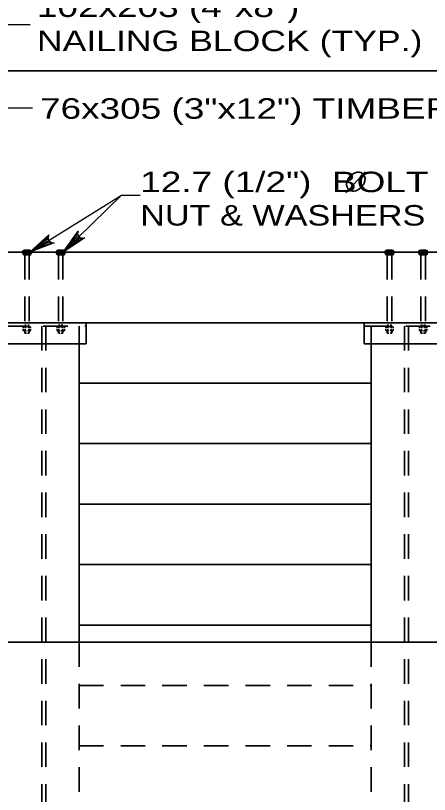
# Model space of a CAD drawing. Extents: x -6.4 to 73.1, y -66 to 0.
# Drawn here: x 44.097 to 46.524, y -63.125 to -58.56 of the extents above; entities that cross this region are included whole.
import ezdxf

# ---------------------------------------------------------------- set-up
doc = ezdxf.new("R2010")
doc.units = 0
doc.header["$LTSCALE"] = 0.048
doc.header["$PDMODE"] = 32
doc.header["$PDSIZE"] = 0.024
doc.linetypes.add('MEDIUM_DASHED', pattern=[4.5, 3, -1.5])
for name, color, linetype, lineweight in [('3', 7, 'Continuous', 35), ('4', 7, 'Continuous', 25), ('5', 7, 'Continuous', 25), ('52', 7, 'Continuous', 25), ('8', 7, 'Continuous', 25)]:
    doc.layers.add(name, color=color, linetype=linetype, lineweight=lineweight)

msp = doc.modelspace()

# ---------------------------------------------------------------- linework, layer by layer
at = {"layer": '3'}
for p, q in [((42.61283, -58.88358), (48.03658, -58.88358)), ((41.76775, -59.9465), (48.03658, -59.9465)), ((44.1425, -59.96242), (44.1425, -59.95025)), ((44.18017, -59.9465), (44.14783, -59.9465)), ((44.1535, -59.95025), (44.1535, -59.96242)), ((44.17483, -59.95025), (44.17483, -59.96242)), ((44.34033, -59.96242), (44.34033, -59.95025)), ((44.383, -59.96242), (44.34033, -59.96242)), ((44.34525, -59.9465), (44.37767, -59.9465)), ((44.35058, -59.95025), (44.35058, -59.96242)), ((44.37192, -59.95025), (44.37192, -59.96242)), ((44.383, -59.96242), (44.383, -59.95025)), ((46.2685, -59.96242), (46.2685, -59.95025)), ((46.30617, -59.9465), (46.27383, -59.9465)), ((46.2795, -59.95025), (46.2795, -59.96242)), ((46.30083, -59.95025), (46.30083, -59.96242)), ((46.46633, -59.96242), (46.46633, -59.95025)), ((46.50892, -59.96242), (46.46633, -59.96242)), ((46.47125, -59.9465), (46.50358, -59.9465)), ((46.47658, -59.95025), (46.47658, -59.96242)), ((46.49792, -59.95025), (46.49792, -59.96242)), ((46.50892, -59.96242), (46.50892, -59.95025)), ((41.76775, -60.35992), (48.03658, -60.35992)), ((44.14208, -60.39133), (44.14208, -60.386)), ((44.17983, -60.38225), (44.14742, -60.38225)), ((44.15958, -60.375), (44.15067, -60.375)), ((44.15317, -60.386), (44.15317, -60.39133)), ((44.17692, -60.375), (44.16858, -60.375)), ((44.1745, -60.386), (44.1745, -60.39133)), ((44.18475, -60.39133), (44.18475, -60.386)), ((44.34067, -60.39192), (44.34067, -60.386)), ((44.34567, -60.38225), (44.378, -60.38225)), ((44.3485, -60.375), (44.358, -60.375)), ((44.351, -60.386), (44.351, -60.39192)), ((44.36517, -60.375), (44.37475, -60.375)), ((44.37233, -60.386), (44.37233, -60.39192)), ((44.38333, -60.39192), (44.38333, -60.386)), ((44.51033, -60.35992), (44.51033, -60.48292)), ((46.14117, -60.35992), (46.14117, -60.48292)), ((46.26808, -60.39133), (46.26808, -60.386)), ((46.30583, -60.38225), (46.27342, -60.38225)), ((46.28558, -60.375), (46.27667, -60.375)), ((46.27917, -60.386), (46.27917, -60.39133)), ((46.30292, -60.375), (46.29458, -60.375)), ((46.3005, -60.386), (46.3005, -60.39133)), ((46.31075, -60.39133), (46.31075, -60.386)), ((46.46667, -60.39192), (46.46667, -60.386)), ((46.47167, -60.38225), (46.504, -60.38225)), ((46.4745, -60.375), (46.484, -60.375)), ((46.477, -60.386), (46.477, -60.39192)), ((46.49117, -60.375), (46.50075, -60.375)), ((46.49833, -60.386), (46.49833, -60.39192)), ((46.50933, -60.39192), (46.50933, -60.386)), ((44.14208, -60.40433), (44.14208, -60.39808)), ((44.1585, -60.40808), (44.14742, -60.40808)), ((44.15067, -60.40808), (44.15067, -60.42092)), ((44.16017, -60.42092), (44.15067, -60.42092)), ((44.15317, -60.39808), (44.15317, -60.40433)), ((44.17692, -60.42092), (44.16742, -60.42092)), ((44.17983, -60.40808), (44.169, -60.40808)), ((44.1745, -60.39808), (44.1745, -60.40433)), ((44.17692, -60.40808), (44.17692, -60.42092)), ((44.18475, -60.40433), (44.18475, -60.39808)), ((44.34067, -60.40433), (44.34067, -60.398)), ((44.34567, -60.40808), (44.358, -60.40808)), ((44.3485, -60.40808), (44.3485, -60.42092)), ((44.3485, -60.42092), (44.358, -60.42092)), ((44.351, -60.398), (44.351, -60.40433)), ((44.364, -60.40808), (44.378, -60.40808)), ((44.364, -60.42092), (44.37475, -60.42092)), ((44.37233, -60.398), (44.37233, -60.40433)), ((44.37475, -60.40808), (44.37475, -60.42092)), ((44.38333, -60.40433), (44.38333, -60.398)), ((46.26808, -60.40433), (46.26808, -60.39808)), ((46.2845, -60.40808), (46.27342, -60.40808)), ((46.27667, -60.40808), (46.27667, -60.42092)), ((46.28617, -60.42092), (46.27667, -60.42092)), ((46.27917, -60.39808), (46.27917, -60.40433)), ((46.30292, -60.42092), (46.29342, -60.42092)), ((46.30583, -60.40808), (46.295, -60.40808)), ((46.3005, -60.39808), (46.3005, -60.40433)), ((46.30292, -60.40808), (46.30292, -60.42092)), ((46.31075, -60.40433), (46.31075, -60.39808)), ((46.46667, -60.40433), (46.46667, -60.398)), ((46.47167, -60.40808), (46.484, -60.40808)), ((46.4745, -60.40808), (46.4745, -60.42092)), ((46.4745, -60.42092), (46.484, -60.42092)), ((46.477, -60.398), (46.477, -60.40433)), ((46.49, -60.40808), (46.504, -60.40808)), ((46.49, -60.42092), (46.50075, -60.42092)), ((46.49833, -60.398), (46.49833, -60.40433)), ((46.50075, -60.40808), (46.50075, -60.42092)), ((46.50933, -60.40433), (46.50933, -60.398)), ((44.01517, -60.48292), (44.51033, -60.48292)), ((44.46933, -60.48292), (44.46933, -62.23267)), ((46.14117, -60.48292), (46.63633, -60.48292)), ((46.18208, -60.48292), (46.18208, -62.23267)), ((44.46933, -60.71425), (46.18208, -60.71425)), ((44.46933, -61.06858), (46.18208, -61.06858)), ((44.46933, -61.42292), (46.18208, -61.42292)), ((44.46933, -61.77725), (46.18208, -61.77725)), ((44.46933, -62.13158), (46.18208, -62.13158)), ((42.0525, -62.23267), (48.03658, -62.23267))]:
    msp.add_line(p, q, dxfattribs=at)
at = {"layer": '3', "linetype": 'MEDIUM_DASHED'}
for p, q in [((44.15067, -59.96242), (44.15067, -60.38225)), ((44.17692, -59.96242), (44.17692, -60.38225)), ((44.3485, -59.96242), (44.3485, -60.38225)), ((44.37475, -59.96242), (44.37475, -60.38225)), ((46.27667, -59.96242), (46.27667, -60.38225)), ((46.30292, -59.96242), (46.30292, -60.38225)), ((46.4745, -59.96242), (46.4745, -60.38225)), ((46.50075, -59.96242), (46.50075, -60.38225)), ((44.46933, -62.23267), (44.46933, -64.0185)), ((46.18208, -62.23267), (46.18208, -64.00542)), ((44.46933, -62.48592), (46.18208, -62.48592)), ((44.46933, -62.84025), (46.18208, -62.84025))]:
    msp.add_line(p, q, dxfattribs=at)
at = {"layer": '3'}
for points in [[(44.1425, -59.96242), (44.18517, -59.96242), (44.18517, -59.95025)], [(46.2685, -59.96242), (46.31108, -59.96242), (46.31108, -59.95025)]]:
    msp.add_lwpolyline(points, dxfattribs=at)
for centre, radius, start, end in [((44.14806, -59.95239), 0.00592, 88.17294, 158.71305), ((44.14806, -59.95239), 0.00592, 21.28694, 88.17294), ((44.16424, -59.96343), 0.01696, 51.05, 128.95), ((44.18005, -59.95186), 0.00539, 17.45181, 162.54819), ((44.34552, -59.95186), 0.00539, 17.45181, 162.54819), ((44.36132, -59.96343), 0.01696, 51.05, 128.95), ((44.37751, -59.95239), 0.00592, 91.82706, 158.71306), ((44.37751, -59.95239), 0.00592, 21.28694, 91.82706), ((46.27403, -59.95242), 0.00592, 88.17294, 158.71305), ((46.27403, -59.95242), 0.00592, 21.28694, 88.17294), ((46.29021, -59.96346), 0.01696, 51.05, 128.95), ((46.30601, -59.95188), 0.00539, 17.45181, 162.54819), ((46.47149, -59.95188), 0.00539, 17.45181, 162.54819), ((46.48729, -59.96346), 0.01696, 51.05, 128.95), ((46.50347, -59.95242), 0.00592, 91.82706, 158.71306), ((46.50347, -59.95242), 0.00592, 21.28694, 91.82706), ((44.14765, -60.38818), 0.00592, 88.17294, 158.71305), ((44.14765, -60.38818), 0.00592, 21.28694, 88.17294), ((44.16383, -60.39922), 0.01696, 51.05, 128.95), ((44.17964, -60.38764), 0.00539, 17.45181, 162.54819), ((44.34587, -60.38764), 0.00539, 17.45181, 162.54819), ((44.36167, -60.39922), 0.01696, 51.05, 128.95), ((44.37785, -60.38818), 0.00592, 91.82706, 158.71306), ((44.37785, -60.38818), 0.00592, 21.28694, 91.82706), ((46.27365, -60.38818), 0.00592, 88.17294, 158.71305), ((46.27365, -60.38818), 0.00592, 21.28694, 88.17294), ((46.28983, -60.39922), 0.01696, 51.05, 128.95), ((46.30564, -60.38764), 0.00539, 17.45181, 162.54819), ((46.47187, -60.38764), 0.00539, 17.45181, 162.54819), ((46.48767, -60.39922), 0.01696, 51.05, 128.95), ((46.50385, -60.38818), 0.00592, 91.82706, 158.71306), ((46.50385, -60.38818), 0.00592, 21.28694, 91.82706), ((44.14765, -60.40216), 0.00592, 201.28694, 271.82706), ((44.14765, -60.40216), 0.00592, 271.82706, 338.71306), ((44.16383, -60.39113), 0.01696, 231.05, 256.0077), ((44.16383, -60.39113), 0.01696, 284.34274, 308.95), ((44.17964, -60.4027), 0.00539, 197.45181, 342.54819), ((44.34587, -60.4027), 0.00539, 197.45181, 342.54819), ((44.36167, -60.39113), 0.01696, 231.05, 257.49177), ((44.36167, -60.39113), 0.01696, 277.88621, 308.95), ((44.37785, -60.40216), 0.00592, 201.28694, 268.17294), ((44.37785, -60.40216), 0.00592, 268.17294, 338.71305), ((46.27365, -60.40216), 0.00592, 201.28694, 271.82706), ((46.27365, -60.40216), 0.00592, 271.82706, 338.71306), ((46.28983, -60.39113), 0.01696, 231.05, 256.0077), ((46.28983, -60.39113), 0.01696, 284.34274, 308.95), ((46.30564, -60.4027), 0.00539, 197.45181, 342.54819), ((46.47187, -60.4027), 0.00539, 197.45181, 342.54819), ((46.48767, -60.39113), 0.01696, 231.05, 257.49177), ((46.48767, -60.39113), 0.01696, 277.88621, 308.95), ((46.50385, -60.40216), 0.00592, 201.28694, 268.17294), ((46.50385, -60.40216), 0.00592, 268.17294, 338.71305)]:
    msp.add_arc(centre, radius, start, end, dxfattribs=at)
for p in [(44.14967, -59.94667), (44.15025, -59.94667), (44.15083, -59.94667), (44.15117, -59.94725), (44.15142, -59.94667), (44.15175, -59.94725), (44.152, -59.94667), (44.152, -59.94783), (44.15233, -59.94725), (44.15258, -59.94667), (44.15258, -59.94783), (44.15292, -59.94725), (44.15292, -59.94842), (44.15325, -59.94667), (44.15325, -59.94783), (44.15325, -59.949), (44.1535, -59.94725), (44.1535, -59.94842), (44.1535, -59.94958), (44.15383, -59.94667), (44.15383, -59.94783), (44.15383, -59.949), (44.15408, -59.94725), (44.15408, -59.94842), (44.15408, -59.94958), (44.15442, -59.94667), (44.15442, -59.94783), (44.15442, -59.949), (44.15467, -59.94725), (44.15467, -59.94842), (44.155, -59.94667), (44.155, -59.94783), (44.155, -59.949), (44.15525, -59.94725), (44.15525, -59.94842), (44.15558, -59.94667), (44.15558, -59.94783), (44.15583, -59.94725), (44.15583, -59.94842), (44.15617, -59.94667), (44.15617, -59.94783), (44.15642, -59.94725), (44.15675, -59.94667), (44.15675, -59.94783), (44.15708, -59.94725), (44.15733, -59.94667), (44.15733, -59.94783), (44.15758, -59.94725), (44.15792, -59.94667), (44.15825, -59.94725), (44.1585, -59.94667), (44.15883, -59.94725), (44.15908, -59.94667), (44.15967, -59.94667), (44.16033, -59.94667), (44.16092, -59.94667), (44.1615, -59.94667), (44.16675, -59.94667), (44.16742, -59.94667), (44.168, -59.94667), (44.16858, -59.94667), (44.16917, -59.94667), (44.16942, -59.94725), (44.16975, -59.94667), (44.17, -59.94725), (44.17033, -59.94667), (44.17067, -59.94725), (44.17092, -59.94667), (44.17092, -59.94783), (44.17125, -59.94725), (44.1715, -59.94667), (44.1715, -59.94783), (44.17183, -59.94725), (44.17208, -59.94667), (44.17208, -59.94783), (44.17242, -59.94725), (44.17242, -59.94842), (44.17275, -59.94667), (44.17275, -59.94783), (44.173, -59.94725), (44.173, -59.94842), (44.17325, -59.94667), (44.17325, -59.94783), (44.17325, -59.949), (44.17358, -59.94725), (44.17358, -59.94842), (44.17392, -59.94667), (44.17392, -59.94783), (44.17392, -59.949), (44.17417, -59.94725), (44.17417, -59.94842), (44.17417, -59.94958), (44.1745, -59.94667), (44.1745, -59.94783), (44.1745, -59.949), (44.17475, -59.94725), (44.17475, -59.94842), (44.17475, -59.94958), (44.17483, -59.94725), (44.17483, -59.94842), (44.17483, -59.94958), (44.17517, -59.94667), (44.17517, -59.94783), (44.17517, -59.949), (44.17542, -59.94842), (44.1755, -59.94725), (44.17575, -59.94667), (44.17575, -59.94783), (44.176, -59.94725), (44.17633, -59.94667), (44.17633, -59.94783), (44.17667, -59.94725), (44.17692, -59.94667), (44.17725, -59.94725), (44.1775, -59.94667), (44.17808, -59.94667), (44.17875, -59.94667), (44.34675, -59.94667), (44.34733, -59.94667), (44.34792, -59.94667), (44.34825, -59.94725), (44.3485, -59.94667), (44.34883, -59.94725), (44.34908, -59.94667), (44.34908, -59.94783), (44.34942, -59.94725), (44.34967, -59.94667), (44.34967, -59.94783), (44.35, -59.94725), (44.35, -59.94842), (44.35033, -59.94667), (44.35033, -59.94783), (44.35033, -59.949), (44.35058, -59.94725), (44.35058, -59.94842), (44.35058, -59.94958), (44.35067, -59.94725), (44.35067, -59.94842), (44.35067, -59.94958), (44.351, -59.94667), (44.351, -59.94783), (44.351, -59.949), (44.35133, -59.94725), (44.35133, -59.94842), (44.35133, -59.94958), (44.35158, -59.94667), (44.35158, -59.94783), (44.35158, -59.949), (44.35183, -59.94725), (44.35183, -59.94842), (44.35217, -59.94667), (44.35217, -59.94783), (44.35217, -59.949), (44.35242, -59.94725), (44.35242, -59.94842), (44.35275, -59.94667), (44.35275, -59.94783), (44.35308, -59.94725), (44.35308, -59.94842), (44.35333, -59.94667), (44.35333, -59.94783), (44.35367, -59.94725), (44.35392, -59.94667), (44.35392, -59.94783), (44.35425, -59.94725), (44.3545, -59.94667), (44.3545, -59.94783), (44.35483, -59.94725), (44.35508, -59.94667), (44.35542, -59.94725), (44.35567, -59.94667), (44.356, -59.94725), (44.35633, -59.94667), (44.35692, -59.94667), (44.3575, -59.94667), (44.35808, -59.94667), (44.35867, -59.94667), (44.364, -59.94667), (44.36458, -59.94667), (44.36517, -59.94667), (44.36575, -59.94667), (44.36633, -59.94667), (44.36667, -59.94725), (44.36692, -59.94667), (44.36725, -59.94725), (44.3675, -59.94667), (44.36783, -59.94725), (44.36808, -59.94667), (44.36808, -59.94783), (44.36842, -59.94725), (44.36875, -59.94667), (44.36875, -59.94783), (44.369, -59.94725), (44.36925, -59.94667), (44.36925, -59.94783), (44.36958, -59.94725), (44.36958, -59.94842), (44.36983, -59.94667), (44.36983, -59.94783), (44.37017, -59.94725), (44.37017, -59.94842), (44.3705, -59.94667), (44.3705, -59.94783), (44.3705, -59.949), (44.37075, -59.94725), (44.37075, -59.94842), (44.37108, -59.94667), (44.37108, -59.94783), (44.37108, -59.949), (44.37133, -59.94725), (44.37133, -59.94842), (44.37133, -59.94958), (44.37167, -59.94667), (44.37167, -59.94783), (44.37167, -59.949), (44.37192, -59.94725), (44.37192, -59.94842), (44.37192, -59.94958), (44.37225, -59.94667), (44.37225, -59.94783), (44.37225, -59.949), (44.3725, -59.94842), (44.37258, -59.94725), (44.37283, -59.94667), (44.37283, -59.94783), (44.37308, -59.94725), (44.37342, -59.94667), (44.37342, -59.94783), (44.37375, -59.94725), (44.374, -59.94667), (44.37433, -59.94725), (44.37458, -59.94667), (44.37517, -59.94667), (44.37583, -59.94667), (46.27567, -59.94667), (46.27625, -59.94667), (46.27683, -59.94667), (46.27708, -59.94725), (46.27742, -59.94667), (46.27775, -59.94725), (46.278, -59.94667), (46.278, -59.94783), (46.27833, -59.94725), (46.27858, -59.94667), (46.27858, -59.94783), (46.27892, -59.94725), (46.27892, -59.94842), (46.27917, -59.94667), (46.27917, -59.94783), (46.27917, -59.949), (46.2795, -59.94725), (46.2795, -59.94842), (46.2795, -59.94958), (46.27983, -59.94667), (46.27983, -59.94783), (46.27983, -59.949), (46.28008, -59.94725), (46.28008, -59.94842), (46.28008, -59.94958), (46.28033, -59.94667), (46.28033, -59.94783), (46.28033, -59.949), (46.28067, -59.94725), (46.28067, -59.94842), (46.28092, -59.94667), (46.28092, -59.94783), (46.28092, -59.949), (46.28125, -59.94725), (46.28125, -59.94842), (46.28158, -59.94667), (46.28158, -59.94783), (46.28183, -59.94725), (46.28183, -59.94842), (46.28217, -59.94667), (46.28217, -59.94783), (46.28242, -59.94725), (46.28275, -59.94667), (46.28275, -59.94783), (46.283, -59.94725), (46.28333, -59.94667), (46.28333, -59.94783), (46.28358, -59.94725), (46.28392, -59.94667), (46.28417, -59.94725), (46.2845, -59.94667), (46.28483, -59.94725), (46.28508, -59.94667), (46.28567, -59.94667), (46.28625, -59.94667), (46.28692, -59.94667), (46.28742, -59.94667), (46.29275, -59.94667), (46.29333, -59.94667), (46.294, -59.94667), (46.2945, -59.94667), (46.29517, -59.94667), (46.29542, -59.94725), (46.29575, -59.94667), (46.296, -59.94725), (46.29633, -59.94667), (46.29658, -59.94725), (46.29692, -59.94667), (46.29692, -59.94783), (46.29725, -59.94725), (46.2975, -59.94667), (46.2975, -59.94783), (46.29775, -59.94725), (46.29808, -59.94667), (46.29808, -59.94783), (46.29833, -59.94725), (46.29833, -59.94842), (46.29867, -59.94667), (46.29867, -59.94783), (46.299, -59.94725), (46.299, -59.94842), (46.29925, -59.94667), (46.29925, -59.94783), (46.29925, -59.949), (46.29958, -59.94725), (46.29958, -59.94842), (46.29983, -59.94667), (46.29983, -59.94783), (46.29983, -59.949), (46.30017, -59.94725), (46.30017, -59.94842), (46.30017, -59.94958), (46.30042, -59.94667), (46.30042, -59.94783), (46.30042, -59.949), (46.30075, -59.94725), (46.30075, -59.94842), (46.30075, -59.94958), (46.30083, -59.94725), (46.30083, -59.94842), (46.30083, -59.94958), (46.30117, -59.94667), (46.30117, -59.94783), (46.30117, -59.949), (46.30142, -59.94725), (46.30142, -59.94842), (46.30175, -59.94667), (46.30175, -59.94783), (46.302, -59.94725), (46.30233, -59.94667), (46.30233, -59.94783), (46.30258, -59.94725), (46.30292, -59.94667), (46.30325, -59.94725), (46.3035, -59.94667), (46.30408, -59.94667), (46.30467, -59.94667), (46.47275, -59.94667), (46.47333, -59.94667), (46.47392, -59.94667), (46.47417, -59.94725), (46.4745, -59.94667), (46.47483, -59.94725), (46.47508, -59.94667), (46.47508, -59.94783), (46.47542, -59.94725), (46.47567, -59.94667), (46.47567, -59.94783), (46.476, -59.94725), (46.476, -59.94842), (46.47625, -59.94667), (46.47625, -59.94783), (46.47625, -59.949), (46.47658, -59.94725), (46.47658, -59.94842), (46.47658, -59.94958), (46.47667, -59.94725), (46.47667, -59.94842), (46.47667, -59.94958), (46.47692, -59.94667), (46.47692, -59.94783), (46.47692, -59.949), (46.47725, -59.94725), (46.47725, -59.94842), (46.47725, -59.94958), (46.47758, -59.94667), (46.47758, -59.94783), (46.47758, -59.949), (46.47783, -59.94725), (46.47783, -59.94842), (46.47817, -59.94667), (46.47817, -59.94783), (46.47817, -59.949), (46.47842, -59.94725), (46.47842, -59.94842), (46.47875, -59.94667), (46.47875, -59.94783), (46.479, -59.94725), (46.479, -59.94842), (46.47933, -59.94667), (46.47933, -59.94783), (46.47967, -59.94725), (46.47992, -59.94667), (46.47992, -59.94783), (46.48017, -59.94725), (46.4805, -59.94667), (46.4805, -59.94783), (46.48083, -59.94725), (46.48108, -59.94667), (46.48142, -59.94725), (46.48167, -59.94667), (46.482, -59.94725), (46.48225, -59.94667), (46.48292, -59.94667), (46.48342, -59.94667), (46.48408, -59.94667), (46.48467, -59.94667), (46.49, -59.94667), (46.4905, -59.94667), (46.49117, -59.94667), (46.49175, -59.94667), (46.49233, -59.94667), (46.49258, -59.94725), (46.49292, -59.94667), (46.49325, -59.94725), (46.4935, -59.94667), (46.49383, -59.94725), (46.49408, -59.94667), (46.49408, -59.94783), (46.49433, -59.94725), (46.49467, -59.94667), (46.49467, -59.94783), (46.495, -59.94725), (46.49525, -59.94667), (46.49525, -59.94783), (46.49558, -59.94725), (46.49558, -59.94842), (46.49583, -59.94667), (46.49583, -59.94783), (46.49617, -59.94725), (46.49617, -59.94842), (46.49642, -59.94667), (46.49642, -59.94783), (46.49642, -59.949), (46.49675, -59.94725), (46.49675, -59.94842), (46.49708, -59.94667), (46.49708, -59.94783), (46.49708, -59.949), (46.49733, -59.94725), (46.49733, -59.94842), (46.49733, -59.94958), (46.49758, -59.94667), (46.49758, -59.94783), (46.49758, -59.949), (46.49792, -59.94725), (46.49792, -59.94842), (46.49792, -59.94958), (46.49825, -59.94667), (46.49825, -59.94783), (46.49825, -59.949), (46.4985, -59.94725), (46.4985, -59.94842), (46.49883, -59.94667), (46.49883, -59.94783), (46.49908, -59.94725), (46.49942, -59.94667), (46.49942, -59.94783), (46.49967, -59.94725), (46.5, -59.94667), (46.50033, -59.94725), (46.50058, -59.94667), (46.50117, -59.94667), (46.50175, -59.94667)]:
    msp.add_point(p, dxfattribs=at)
at = {"layer": '4'}
for p, q in [((44.03408, -58.61142), (44.18167, -58.61142)), ((44.04825, -59.10017), (44.19575, -59.10017)), ((44.18108, -59.94658), (44.71867, -59.61175))]:
    msp.add_line(p, q, dxfattribs=at)
msp.add_lwpolyline([(44.37625, -59.9465), (44.71867, -59.61175), (44.82825, -59.61175)], dxfattribs=at)
at = {"layer": '5', "lineweight": 35}
msp.add_line((46.03433, -59.59875), (46.14633, -59.47617), dxfattribs=at)
msp.add_spline([(46.13467, -59.48825), (46.12592, -59.48142), (46.11717, -59.479), (46.10617, -59.478), (46.09992, -59.478), (46.08917, -59.4805), (46.07933, -59.485), (46.07242, -59.48892), (46.05917, -59.4995), (46.04883, -59.513), (46.04258, -59.52567), (46.03892, -59.53725), (46.03783, -59.548), (46.03892, -59.55725), (46.04342, -59.57042), (46.04817, -59.57725), (46.05783, -59.5845), (46.07233, -59.588), (46.08883, -59.5875), (46.10967, -59.578), (46.12492, -59.56492), (46.13642, -59.549), (46.14392, -59.53242), (46.14642, -59.514), (46.14317, -59.50217), (46.13517, -59.48825)], degree=3, dxfattribs=at)
at = {"layer": '52'}
for points in [[(44.18108, -59.94658), (44.29292, -59.844), (44.28733, -59.85683), (44.28758, -59.8685), (44.29142, -59.87783), (44.29817, -59.88542), (44.3085, -59.89075), (44.32242, -59.8915), (44.18108, -59.94658), (44.3085, -59.89075), (44.29817, -59.88542), (44.18108, -59.94658), (44.29142, -59.87783), (44.28758, -59.8685), (44.18108, -59.94658), (44.28733, -59.85683)], [(44.37625, -59.9465), (44.46333, -59.82225), (44.46067, -59.836), (44.46342, -59.84725), (44.46925, -59.85558), (44.47742, -59.86158), (44.48867, -59.86458), (44.50242, -59.86225), (44.37625, -59.9465), (44.48867, -59.86458), (44.47742, -59.86158), (44.37625, -59.9465), (44.46925, -59.85558), (44.46342, -59.84725), (44.37625, -59.9465), (44.46067, -59.836)]]:
    msp.add_lwpolyline(points, dxfattribs=at)
at = {"layer": '8', "linetype": 'MEDIUM_DASHED', "lineweight": 35}
for p, q in [((44.01517, -60.37958), (44.51033, -60.37958)), ((44.251, -60.37958), (44.251, -64.01408)), ((44.27467, -60.37958), (44.27467, -64.02892)), ((44.46933, -60.37958), (44.46933, -60.48292)), ((46.14117, -60.37958), (46.63633, -60.37958)), ((46.18217, -60.37958), (46.18217, -60.48292)), ((46.377, -60.37958), (46.377, -64.01408)), ((46.40058, -60.37958), (46.40058, -64.02892))]:
    msp.add_line(p, q, dxfattribs=at)

# ---------------------------------------------------------------- texts
at = {"layer": '4'}
for s, width, p in [('12.7 (1/2")  BOLT W/ STD.', 1.35, (44.828, -59.5945)), ('NUT & WASHERS (TYP.)', 1.25, (44.828, -59.79033))]:
    msp.add_text(s, height=0.12, dxfattribs=dict(at, width=width)).set_placement(p)
at = {"layer": '5'}
for s, width, p in [('102x203 (4"x8")', 1.35, (44.22225, -58.56783)), ('NAILING BLOCK (TYP.)', 1.3, (44.22225, -58.76783)), ('76x305 (3"x12") TIMBER LAGGING ABUT.', 1.35, (44.24033, -59.16425))]:
    msp.add_text(s, height=0.12, dxfattribs=dict(at, width=width)).set_placement(p)

doc.saveas('drawing.dxf')
